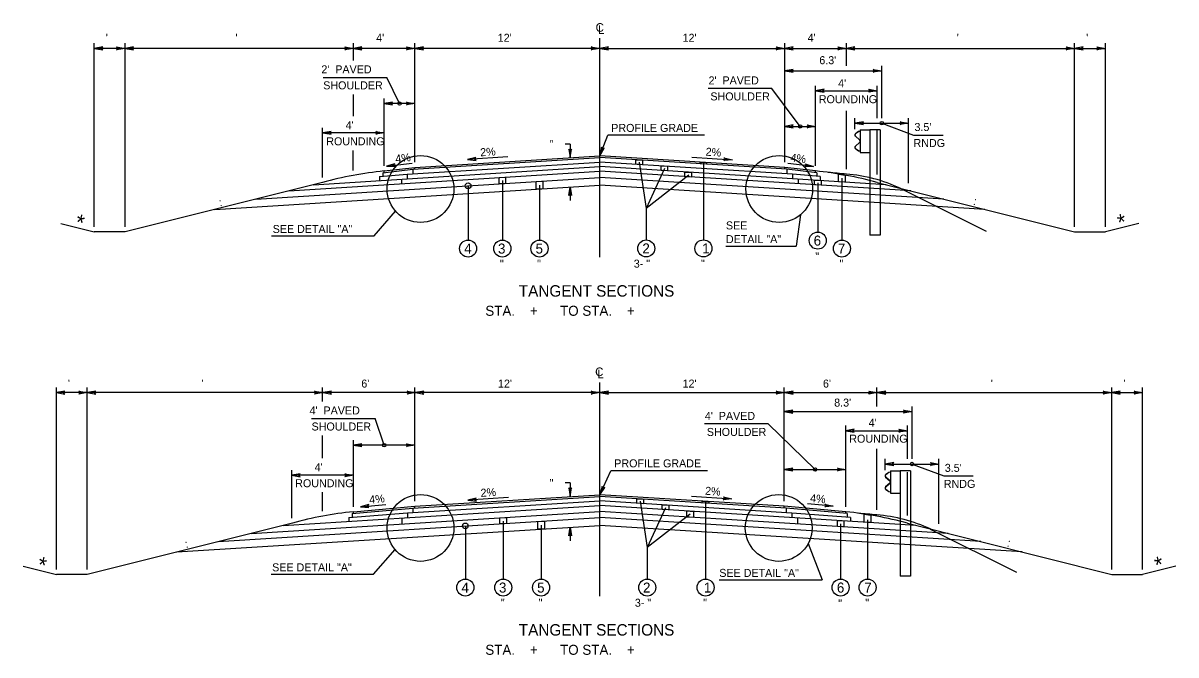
# Model space of a CAD drawing. Extents: x -592 to 1199, y -590 to 416.
# Drawn here: x 137.3 to 338.9, y -214.4 to -104 of the extents above; entities that cross this region are included whole.
import ezdxf

# ---------------------------------------------------------------- set-up
doc = ezdxf.new("R2010")
doc.units = 0
doc.layers.add('1', color=7, linetype='Continuous')
doc.layers.add('Des_ Drain_ Ftrs', color=7, linetype='Continuous')

msp = doc.modelspace()

# ---------------------------------------------------------------- linework, layer by layer
at = {"layer": '1'}
for p, q in [((238.16, -144.86), (238.16, -106.62)), ((149.75, -139.57), (149.75, -107.5)), ((155.13, -108.38), (149.75, -108.38)), ((155.13, -139.57), (155.13, -107.5)), ((195.06, -108.38), (155.13, -108.38)), ((195.06, -110.5), (195.06, -107.5)), ((205.83, -108.38), (195.06, -108.38)), ((205.83, -128.3), (205.83, -107.5)), ((238.16, -108.38), (205.83, -108.38)), ((238.16, -108.38), (270.49, -108.38)), ((270.49, -128.3), (270.49, -107.5)), ((270.49, -108.38), (281.27, -108.38)), ((281.27, -111.45), (281.27, -107.5)), ((281.27, -108.38), (321.19, -108.38)), ((321.19, -139.57), (321.19, -107.5)), ((321.19, -108.38), (326.58, -108.38)), ((326.58, -139.57), (326.58, -107.5)), ((270.49, -112.3), (287.47, -112.3)), ((287.47, -120.58), (287.47, -111.42)), ((189.79, -113.45), (200.93, -113.45)), ((203.14, -118.03), (200.93, -113.45)), ((275.88, -128.93), (275.88, -114.91)), ((286.66, -120.58), (286.66, -114.91)), ((195.06, -120.25), (195.06, -116.46)), ((268.22, -115.38), (257.08, -115.38)), ((273.19, -122.02), (268.22, -115.38)), ((275.88, -115.79), (286.66, -115.79)), ((200.44, -128.93), (200.44, -117.15)), ((205.83, -118.03), (200.44, -118.03)), ((281.27, -129.49), (281.27, -119.32)), ((282.77, -122.53), (282.77, -120.58)), ((292.16, -131.93), (292.16, -120.58)), ((189.66, -130.94), (189.66, -122.26)), ((270.49, -122.02), (275.88, -122.02)), ((282.77, -121.46), (292.16, -121.46)), ((283.37, -122.92), (282.85, -123.31)), ((283.38, -122.95), (282.87, -123.34)), ((283.69, -122.87), (283.37, -122.92)), ((283.69, -122.9), (283.38, -122.95)), ((283.69, -122.64), (283.69, -126.57)), ((283.69, -122.64), (285.37, -122.64)), ((285.37, -122.64), (285.37, -141.04)), ((287.2, -122.64), (285.37, -122.64)), ((286.66, -130.45), (286.66, -122.56)), ((287.2, -122.64), (287.2, -141.04)), ((287.47, -121.46), (293.02, -123.53)), ((200.44, -123.14), (189.67, -123.14)), ((238.16, -127.15), (239.54, -123.57)), ((256.46, -123.57), (239.54, -123.57)), ((282.84, -123.75), (283.57, -124.38)), ((283.57, -124.83), (282.84, -125.47)), ((282.86, -123.72), (283.59, -124.36)), ((283.59, -124.85), (282.86, -125.49)), ((283.66, -124.57), (283.66, -124.64)), ((283.69, -124.57), (283.69, -124.64)), ((293.02, -123.53), (298.18, -123.53)), ((195.05, -129.71), (195.05, -126.21)), ((232.98, -125.1), (232.1, -125.1)), ((232.98, -125.1), (232.98, -127.47)), ((282.85, -125.9), (283.37, -126.29)), ((282.87, -125.88), (283.38, -126.26)), ((283.37, -126.29), (283.69, -126.34)), ((283.38, -126.26), (283.69, -126.31)), ((283.69, -126.57), (285.37, -126.57)), ((200.87, -128.98), (205.34, -128.45)), ((204.48, -130.37), (238.16, -128.25)), ((205.47, -129.5), (238.16, -127.44)), ((205.83, -129.18), (238.16, -127.15)), ((222.09, -127.37), (215.02, -127.82)), ((270.49, -129.18), (238.16, -127.15)), ((270.86, -129.5), (238.16, -127.44)), ((271.84, -130.37), (238.16, -128.25)), ((245.03, -128.28), (246.27, -136.4)), ((254.27, -127.4), (261.34, -127.84)), ((256.27, -128.43), (256.27, -141.86)), ((275.51, -129.01), (271.04, -128.48)), ((178.02, -134.73), (238.16, -130.95)), ((183.79, -133.29), (238.16, -129.87)), ((188.11, -132.21), (238.16, -129.06)), ((199.61, -130.8), (204.48, -130.37)), ((199.61, -130.8), (199.61, -131.49)), ((200.2, -130.14), (205.47, -129.5)), ((200.2, -130.14), (200.2, -130.75)), ((200.44, -129.81), (205.83, -129.18)), ((200.44, -130.11), (200.44, -129.81)), ((204.48, -130.37), (204.48, -131.18)), ((205.47, -129.5), (205.47, -130.31)), ((205.83, -129.48), (205.83, -129.18)), ((288.21, -132.21), (238.16, -129.06)), ((292.54, -133.29), (238.16, -129.87)), ((298.3, -134.73), (238.16, -130.95)), ((249.45, -129.38), (246.27, -136.4)), ((253.72, -130.56), (246.27, -136.4)), ((270.49, -129.48), (270.49, -129.18)), ((275.88, -129.81), (270.49, -129.18)), ((270.86, -129.5), (270.86, -130.31)), ((276.12, -130.14), (270.86, -129.5)), ((271.84, -130.37), (271.84, -131.18)), ((276.71, -130.8), (271.84, -130.37)), ((275.88, -130.11), (275.88, -129.81)), ((276.12, -130.14), (276.12, -130.75)), ((276.71, -130.8), (276.71, -131.48)), ((282.77, -130.59), (282.77, -130.59)), ((189.66, -131.82), (155.13, -140.45)), ((170.82, -136.53), (238.16, -132.3)), ((203.49, -131.24), (203.49, -132.05)), ((215.12, -132.4), (215.12, -141.89)), ((221.11, -131.48), (221.11, -141.89)), ((227.61, -132.29), (227.61, -141.89)), ((232.98, -132.62), (232.98, -134.99)), ((305.51, -136.53), (238.16, -132.3)), ((272.83, -131.24), (272.83, -132.05)), ((276.26, -131.91), (276.26, -140.5)), ((280.49, -131.1), (280.49, -141.89)), ((286.66, -131.82), (321.19, -140.45)), ((290.66, -132.82), (305.71, -140.35)), ((198.7, -141.16), (202.44, -136.84)), ((246.27, -136.4), (246.27, -141.87)), ((143.92, -139), (149.75, -140.45)), ((273.22, -137.48), (272.5, -142.93)), ((332.4, -138.99), (326.58, -140.45)), ((155.13, -140.45), (149.75, -140.45)), ((287.2, -141.04), (285.37, -141.04)), ((321.19, -140.45), (326.58, -140.45)), ((180.76, -141.16), (198.7, -141.16)), ((260.2, -142.93), (272.5, -142.93)), ((238.16, -204.12), (238.16, -166.8)), ((143.13, -199.45), (143.13, -167.68)), ((148.51, -168.56), (143.13, -168.56)), ((148.51, -199.45), (148.51, -167.68)), ((189.76, -168.56), (148.51, -168.56)), ((189.67, -170.11), (189.67, -167.68)), ((205.92, -168.56), (189.76, -168.56)), ((205.83, -187.55), (205.83, -167.68)), ((238.16, -168.56), (205.92, -168.56)), ((238.16, -168.56), (270.49, -168.56)), ((270.4, -187.55), (270.4, -167.68)), ((270.49, -168.56), (286.66, -168.56)), ((286.57, -171), (286.57, -167.68)), ((286.66, -168.56), (327.69, -168.56)), ((327.69, -199.45), (327.69, -167.68)), ((327.69, -168.56), (333.07, -168.56)), ((333.07, -199.45), (333.07, -167.68)), ((292.76, -180.16), (292.76, -171)), ((187.76, -173.08), (198.9, -173.08)), ((200.45, -177.75), (198.9, -173.08)), ((270.4, -171.88), (292.76, -171.88)), ((267.6, -174.03), (256.46, -174.03)), ((275.79, -182), (267.6, -174.03)), ((281.17, -175.21), (291.95, -175.21)), ((281.18, -188.51), (281.18, -174.33)), ((291.96, -180.16), (291.96, -174.33)), ((189.67, -180.02), (189.67, -176.06)), ((195.06, -188.5), (195.06, -176.87)), ((205.83, -177.75), (195.06, -177.75)), ((286.57, -189.07), (286.57, -178.4)), ((288.07, -182.11), (288.07, -180.16)), ((288.07, -181.04), (297.45, -181.04)), ((292.76, -181.04), (298.32, -183.11)), ((297.45, -191.5), (297.45, -180.16)), ((184.28, -190.51), (184.28, -182.12)), ((195.06, -183), (184.28, -183)), ((238.16, -186.4), (240.07, -182.21)), ((256.99, -182.21), (240.07, -182.21)), ((270.4, -182), (281.18, -182)), ((288.14, -183.33), (288.87, -183.96)), ((288.67, -182.5), (288.15, -182.89)), ((288.16, -183.3), (288.89, -183.94)), ((288.68, -182.53), (288.17, -182.92)), ((288.98, -182.45), (288.67, -182.5)), ((288.98, -182.48), (288.68, -182.53)), ((288.98, -182.22), (288.98, -186.15)), ((288.98, -182.22), (290.67, -182.22)), ((290.67, -182.22), (290.67, -200.62)), ((292.49, -182.22), (290.67, -182.22)), ((291.96, -190.03), (291.96, -182.47)), ((292.49, -182.22), (292.49, -200.62)), ((298.32, -183.11), (303.47, -183.11)), ((232.96, -184.35), (232.08, -184.35)), ((232.96, -184.35), (232.96, -186.72)), ((288.87, -184.41), (288.14, -185.05)), ((288.89, -184.43), (288.16, -185.07)), ((288.17, -185.45), (288.68, -185.84)), ((288.95, -184.15), (288.95, -184.22)), ((288.98, -184.15), (288.98, -184.22)), ((189.67, -189.28), (189.67, -185.95)), ((204.5, -189.6), (238.16, -187.49)), ((205.47, -188.75), (238.16, -186.69)), ((205.83, -188.42), (238.16, -186.4)), ((222.16, -186.91), (215.08, -187.35)), ((270.4, -188.43), (238.16, -186.4)), ((270.77, -188.75), (238.16, -186.7)), ((254.16, -186.67), (261.24, -187.12)), ((288.15, -185.48), (288.67, -185.87)), ((288.67, -185.87), (288.98, -185.92)), ((288.68, -185.84), (288.98, -185.89)), ((288.98, -186.15), (290.67, -186.15)), ((177.16, -193.17), (238.16, -189.34)), ((182.78, -191.77), (238.16, -188.28)), ((194.82, -189.7), (205.47, -188.75)), ((195.06, -189.38), (205.83, -188.42)), ((195.06, -189.68), (195.06, -189.38)), ((196.28, -188.5), (200.76, -188.11)), ((205.47, -188.75), (205.47, -189.54)), ((205.83, -188.72), (205.83, -188.42)), ((271.74, -189.61), (238.16, -187.5)), ((293.44, -191.77), (238.16, -188.29)), ((299.06, -193.17), (238.16, -189.34)), ((245.22, -187.56), (246.46, -195.66)), ((249.63, -188.67), (246.46, -195.66)), ((256.65, -187.7), (256.65, -201.15)), ((270.4, -188.73), (270.4, -188.43)), ((281.18, -189.39), (270.4, -188.43)), ((281.42, -189.71), (270.77, -188.75)), ((270.77, -188.75), (270.77, -189.55)), ((278.98, -188.42), (274.5, -188.02)), ((281.18, -189.69), (281.18, -189.39)), ((184.41, -191.36), (148.51, -200.33)), ((171.43, -194.6), (238.16, -190.41)), ((194.26, -190.36), (204.5, -189.6)), ((194.26, -190.36), (194.26, -191.04)), ((194.82, -189.7), (194.82, -190.32)), ((203.53, -190.46), (203.53, -191.51)), ((204.5, -189.6), (204.5, -190.4)), ((221.27, -191.02), (221.27, -201.15)), ((304.78, -194.6), (238.16, -190.41)), ((253.97, -189.78), (246.46, -195.66)), ((271.74, -189.61), (271.74, -190.41)), ((281.98, -190.36), (271.76, -189.62)), ((272.72, -190.47), (272.72, -191.52)), ((280.27, -191.47), (280.27, -201.15)), ((281.42, -189.71), (281.42, -190.32)), ((281.98, -190.36), (281.98, -191.05)), ((284.99, -190.82), (284.99, -201.15)), ((288.07, -190.17), (288.07, -190.17)), ((291.96, -191.4), (327.69, -200.33)), ((164.2, -196.41), (238.16, -191.76)), ((214.64, -191.85), (214.64, -201.15)), ((227.88, -191.75), (227.88, -201.15)), ((232.96, -192.09), (232.96, -194.46)), ((312.01, -196.41), (238.16, -191.77)), ((295.95, -192.4), (311.01, -199.93)), ((274.61, -194.93), (277.04, -201.27)), ((198.6, -200.3), (202.34, -195.98)), ((246.46, -195.66), (246.46, -201.15)), ((137.3, -198.87), (143.13, -200.33)), ((338.9, -198.87), (333.07, -200.33)), ((148.51, -200.33), (143.13, -200.33)), ((180.67, -200.3), (198.6, -200.3)), ((259.04, -201.27), (277.04, -201.27)), ((292.49, -200.62), (290.67, -200.62)), ((327.69, -200.33), (333.07, -200.33))]:
    msp.add_line(p, q, dxfattribs=at)
for points in [[(244.46, -127.84), (245.6, -127.91), (245.6, -128.72), (244.46, -128.65)], [(248.86, -128.93), (250.01, -129), (250.01, -129.81), (248.86, -129.73)], [(255.7, -128.25), (256.84, -128.32), (256.84, -128.62), (255.7, -128.55)], [(220.54, -130.98), (221.68, -130.91), (221.68, -131.99), (220.54, -132.06)], [(253.05, -130), (254.2, -130.07), (254.2, -130.88), (253.05, -130.81)], [(279.92, -130.35), (281.06, -130.55), (281.06, -131.76), (279.92, -131.69)], [(227.04, -131.65), (228.18, -131.58), (228.18, -132.93), (227.04, -133)], [(275.69, -131.42), (276.84, -131.49), (276.84, -132.3), (275.69, -132.23)], [(244.65, -187.11), (245.8, -187.18), (245.8, -187.98), (244.65, -187.9)], [(249.05, -188.18), (250.2, -188.25), (250.2, -189.05), (249.05, -188.98)], [(253.4, -189.25), (254.54, -189.32), (254.54, -190.37), (253.4, -190.3)], [(256.08, -187.53), (257.23, -187.6), (257.23, -187.9), (256.08, -187.83)], [(220.7, -190.43), (221.84, -190.36), (221.84, -191.43), (220.7, -191.5)], [(227.31, -191.09), (228.46, -191.02), (228.46, -192.37), (227.31, -192.44)], [(279.7, -190.91), (280.84, -190.98), (280.84, -192.03), (279.7, -191.96)], [(284.41, -189.8), (285.56, -189.99), (285.56, -191.27), (284.41, -191.2)]]:
    msp.add_lwpolyline(points, close=True, dxfattribs=at)
for centre, radius in [((203.14, -118.03), 0.3), ((273.19, -122.02), 0.3), ((287.47, -121.46), 0.3), ((206.8, -132.96), 5.84), ((269.53, -132.96), 5.84), ((215.12, -132.4), 0.5), ((276.26, -141.99), 1.49), ((215.12, -143.38), 1.49), ((221.11, -143.38), 1.49), ((227.61, -143.38), 1.49), ((246.27, -143.35), 1.49), ((256.27, -143.34), 1.49), ((280.49, -143.38), 1.49), ((200.45, -177.75), 0.3), ((292.76, -181.04), 0.3), ((275.79, -182), 0.3), ((206.8, -192.21), 5.84), ((269.44, -192.21), 5.84), ((214.64, -191.85), 0.5), ((214.64, -202.63), 1.49), ((221.27, -202.63), 1.49), ((227.88, -202.63), 1.49), ((246.46, -202.63), 1.49), ((256.65, -202.63), 1.49), ((280.27, -202.63), 1.49), ((284.99, -202.63), 1.49)]:
    msp.add_circle(centre, radius, dxfattribs=at)
for centre, radius, start, end in [((283.02, -123.54), 0.278, 126.9799, 229.021), ((283.02, -123.54), 0.249, 126.9799, 229.021), ((283.41, -124.57), 0.249, 0, 49.0365), ((283.41, -124.64), 0.249, 310.9635, 0), ((283.41, -124.57), 0.278, 0, 49.0365), ((283.41, -124.64), 0.278, 310.9635, 0), ((283.02, -125.68), 0.278, 130.979, 233.0201), ((283.02, -125.68), 0.249, 130.979, 233.0201), ((207.32, -196.65), 67.19, 95.8795, 105.2381), ((268.99, -196.64), 67.19, 74.7593, 84.1179), ((270.45, -231.03), 101.24, 83.8633, 85.6775), ((279.15, -157.65), 27.37, 65.1374, 85.5513), ((288.32, -183.12), 0.278, 126.9799, 229.021), ((288.32, -183.12), 0.249, 126.9799, 229.021), ((288.32, -185.26), 0.278, 130.979, 233.0201), ((288.32, -185.26), 0.249, 130.979, 233.0201), ((288.71, -184.15), 0.249, 0, 49.0365), ((288.71, -184.22), 0.249, 310.9635, 0), ((288.71, -184.15), 0.278, 0, 49.0365), ((288.71, -184.22), 0.278, 310.9635, 0), ((201.94, -256.22), 67.19, 95.8795, 105.1262), ((274.3, -256.22), 67.19, 74.7611, 84.1196), ((275.75, -290.61), 101.24, 83.8633, 85.6775), ((284.45, -217.23), 27.37, 65.1374, 85.5513)]:
    msp.add_arc(centre, radius, start, end, dxfattribs=at)
at = {"layer": 'Des_ Drain_ Ftrs'}
for points in [[(149.75, -108.38), (151.23, -108.63), (150.94, -108.38), (151.23, -108.13)], [(155.13, -108.38), (153.65, -108.63), (153.94, -108.38), (153.65, -108.13)], [(155.13, -108.38), (156.62, -108.63), (156.33, -108.38), (156.62, -108.13)], [(195.06, -108.38), (193.57, -108.63), (193.86, -108.38), (193.57, -108.13)], [(195.06, -108.38), (196.54, -108.63), (196.25, -108.38), (196.54, -108.13)], [(205.83, -108.38), (204.34, -108.63), (204.64, -108.38), (204.34, -108.13)], [(205.83, -108.38), (207.32, -108.63), (207.03, -108.38), (207.32, -108.13)], [(238.16, -108.38), (236.67, -108.63), (236.97, -108.38), (236.67, -108.13)], [(238.16, -108.38), (239.65, -108.63), (239.36, -108.38), (239.65, -108.13)], [(270.49, -108.38), (269, -108.63), (269.3, -108.38), (269, -108.13)], [(270.49, -108.38), (271.98, -108.63), (271.69, -108.38), (271.98, -108.13)], [(281.27, -108.38), (279.78, -108.63), (280.07, -108.38), (279.78, -108.13)], [(281.27, -108.38), (282.76, -108.63), (282.46, -108.38), (282.76, -108.13)], [(321.19, -108.38), (319.7, -108.63), (319.99, -108.38), (319.7, -108.13)], [(321.19, -108.38), (322.68, -108.63), (322.38, -108.38), (322.68, -108.13)], [(326.58, -108.38), (325.09, -108.63), (325.38, -108.38), (325.09, -108.13)], [(270.49, -112.3), (271.98, -112.55), (271.69, -112.3), (271.98, -112.05)], [(287.47, -112.3), (285.98, -112.55), (286.27, -112.3), (285.98, -112.05)], [(275.88, -115.79), (277.37, -116.04), (277.07, -115.79), (277.37, -115.54)], [(286.66, -115.79), (285.17, -116.04), (285.46, -115.79), (285.17, -115.54)], [(200.44, -118.03), (201.93, -118.28), (201.64, -118.03), (201.93, -117.78)], [(205.83, -118.03), (204.34, -118.28), (204.64, -118.03), (204.34, -117.78)], [(189.67, -123.14), (191.16, -123.39), (190.86, -123.14), (191.16, -122.89)], [(200.44, -123.14), (198.96, -123.39), (199.25, -123.14), (198.96, -122.89)], [(270.49, -122.02), (271.98, -122.27), (271.69, -122.02), (271.98, -121.77)], [(275.88, -122.02), (274.39, -122.27), (274.69, -122.02), (274.39, -121.77)], [(282.77, -121.46), (284.26, -121.7), (283.97, -121.46), (284.26, -121.21)], [(292.16, -121.46), (290.67, -121.7), (290.96, -121.46), (290.67, -121.21)], [(232.98, -127.47), (233.23, -125.98), (232.98, -126.28), (232.73, -125.98)], [(238.16, -127.15), (238.93, -125.84), (238.59, -126.03), (238.46, -125.67)], [(200.87, -128.98), (202.38, -129.05), (202.06, -128.84), (202.32, -128.56)], [(215.02, -127.82), (216.52, -127.97), (216.21, -127.74), (216.49, -127.48)], [(261.34, -127.84), (259.84, -128), (260.15, -127.77), (259.87, -127.5)], [(275.51, -129.01), (274, -129.08), (274.33, -128.87), (274.06, -128.59)], [(232.98, -132.62), (233.23, -134.11), (232.98, -133.82), (232.73, -134.11)], [(143.13, -168.56), (144.61, -168.81), (144.32, -168.56), (144.61, -168.31)], [(148.51, -168.56), (147.03, -168.81), (147.32, -168.56), (147.03, -168.31)], [(148.51, -168.56), (150, -168.81), (149.71, -168.56), (150, -168.31)], [(189.76, -168.56), (188.27, -168.81), (188.57, -168.56), (188.27, -168.31)], [(189.76, -168.56), (191.25, -168.81), (190.95, -168.56), (191.25, -168.31)], [(205.92, -168.56), (204.44, -168.81), (204.73, -168.56), (204.44, -168.31)], [(205.92, -168.56), (207.41, -168.81), (207.12, -168.56), (207.41, -168.31)], [(238.16, -168.56), (236.67, -168.81), (236.97, -168.56), (236.67, -168.31)], [(238.16, -168.56), (239.65, -168.81), (239.36, -168.56), (239.65, -168.31)], [(270.49, -168.56), (269, -168.81), (269.3, -168.56), (269, -168.31)], [(270.49, -168.56), (271.98, -168.81), (271.69, -168.56), (271.98, -168.31)], [(286.66, -168.56), (285.17, -168.81), (285.46, -168.56), (285.17, -168.31)], [(286.66, -168.56), (288.15, -168.81), (287.85, -168.56), (288.15, -168.31)], [(327.69, -168.56), (326.2, -168.81), (326.49, -168.56), (326.2, -168.31)], [(327.69, -168.56), (329.17, -168.81), (328.88, -168.56), (329.17, -168.31)], [(333.07, -168.56), (331.59, -168.81), (331.88, -168.56), (331.59, -168.31)], [(270.4, -171.88), (271.89, -172.13), (271.59, -171.88), (271.89, -171.63)], [(292.76, -171.88), (291.27, -172.13), (291.57, -171.88), (291.27, -171.63)], [(281.17, -175.21), (282.66, -175.45), (282.37, -175.21), (282.66, -174.96)], [(291.95, -175.21), (290.46, -175.45), (290.76, -175.21), (290.46, -174.96)], [(195.06, -177.75), (196.55, -178), (196.25, -177.75), (196.55, -177.5)], [(205.83, -177.75), (204.35, -178), (204.64, -177.75), (204.35, -177.5)], [(288.07, -181.04), (289.56, -181.28), (289.26, -181.04), (289.56, -180.79)], [(297.45, -181.04), (295.97, -181.28), (296.26, -181.04), (295.97, -180.79)], [(184.28, -183), (185.77, -183.25), (185.47, -183), (185.77, -182.75)], [(195.06, -183), (193.57, -183.25), (193.86, -183), (193.57, -182.75)], [(270.4, -182), (271.89, -182.24), (271.6, -182), (271.89, -181.75)], [(281.18, -182), (279.69, -182.24), (279.99, -182), (279.69, -181.75)], [(232.96, -186.72), (233.21, -185.23), (232.96, -185.53), (232.71, -185.23)], [(238.16, -186.4), (239.01, -185.15), (238.66, -185.32), (238.55, -184.95)], [(215.08, -187.35), (216.59, -187.51), (216.27, -187.28), (216.55, -187.01)], [(261.24, -187.12), (259.74, -187.27), (260.05, -187.04), (259.77, -186.78)], [(196.28, -188.5), (197.78, -188.62), (197.47, -188.4), (197.74, -188.13)], [(278.98, -188.42), (277.48, -188.54), (277.79, -188.31), (277.52, -188.04)], [(232.96, -192.09), (233.21, -193.58), (232.96, -193.28), (232.71, -193.58)]]:
    msp.add_lwpolyline(points, close=True, dxfattribs=at)

# ---------------------------------------------------------------- texts
at = {"layer": '1'}
for s, height, p in [(" '", 1.4, (151.24, -107.23)), ("  '", 1.4, (173.4, -107.23)), ("4'", 1.4, (199.05, -107.23)), ("12'", 1.4, (220.3, -107.23)), ("12'", 1.4, (252.63, -107.23)), ("4'", 1.4, (274.49, -107.23)), ("  '", 1.4, (299.53, -107.23)), (" '", 1.4, (322.69, -107.23)), ("6.3'", 1.4, (276.54, -111.15)), ("2'  PAVED", 1.4, (189.46, -112.75)), ('SHOULDER', 1.4, (189.79, -115.55)), ("2'  PAVED", 1.4, (257.17, -114.68)), ("4'", 1.4, (279.84, -115.17)), ('SHOULDER', 1.4, (257.49, -117.48)), ('ROUNDING', 1.4, (276.45, -117.97)), ("4'", 1.4, (193.7, -122.53)), ('PROFILE GRADE', 1.4, (240.15, -122.99)), ("3.5'", 1.4, (293.18, -122.83)), ('ROUNDING', 1.4, (190.32, -125.33)), ('RNDG', 1.4, (293.01, -125.63)), ('SEE', 1.4, (260.21, -140.03)), ('SEE DETAIL "A"', 1.4, (180.95, -140.65)), ('DETAIL "A"', 1.4, (260.21, -142.43)), ('6', 1.75, (275.55, -142.86)), ('4', 1.75, (214.44, -144.25)), ('3', 1.75, (220.35, -144.25)), ('5', 1.75, (226.92, -144.25)), ('2', 1.75, (245.6, -144.23)), ('1', 1.75, (256.06, -144.22)), ('7', 1.75, (279.78, -144.25)), (' "', 1.4, (275.32, -145.44)), (' "', 1.4, (220.17, -146.74)), (' "', 1.4, (226.67, -146.74)), ('3- "', 1.4, (244.09, -146.71)), (' "', 1.4, (255.33, -146.7)), (' "', 1.4, (279.55, -146.74)), ('TANGENT SECTIONS', 2, (223.99, -151.78)), ('STA.    +      TO STA.    +     ', 1.75, (218.13, -155.13)), (" '", 1.4, (144.62, -167.68)), ("  '", 1.4, (167.44, -167.68)), ("6'", 1.4, (196.45, -167.68)), ("12'", 1.4, (220.35, -167.68)), ("12'", 1.4, (252.63, -167.68)), ("6'", 1.4, (277.18, -167.68)), ("  '", 1.4, (305.48, -167.68)), (" '", 1.4, (329.19, -167.68)), ("4'  PAVED", 1.4, (187.4, -172.38)), ("8.3'", 1.4, (279.14, -171)), ("4'  PAVED", 1.4, (256.52, -173.33)), ("4'", 1.4, (285.17, -174.51)), ('SHOULDER', 1.4, (187.75, -175.18)), ('SHOULDER', 1.4, (256.87, -176.13)), ('ROUNDING', 1.4, (281.78, -177.31)), ("4'", 1.4, (188.28, -182.3)), ('PROFILE GRADE', 1.4, (240.68, -181.62)), ("3.5'", 1.4, (298.48, -182.41)), ('ROUNDING', 1.4, (184.89, -185.1)), ('RNDG', 1.4, (298.31, -185.21)), ('SEE DETAIL "A"', 1.4, (180.86, -199.8)), ('SEE DETAIL "A"', 1.4, (259.05, -200.77)), ('4', 1.75, (213.97, -203.51)), ('3', 1.75, (220.52, -203.51)), ('5', 1.75, (227.19, -203.51)), ('2', 1.75, (245.71, -203.51)), ('1', 1.75, (256.35, -203.51)), ('6', 1.75, (279.61, -203.51)), ('7', 1.75, (284.4, -203.51)), (' "', 1.4, (220.33, -205.99)), (' "', 1.4, (226.94, -205.99)), ('3- "', 1.4, (244.28, -205.99)), (' "', 1.4, (255.71, -205.99)), (' "', 1.4, (279.33, -206.09)), ('  "', 1.4, (283.54, -205.99)), ('TANGENT SECTIONS', 2, (223.99, -211.03)), ('STA.    +      TO STA.    +     ', 1.75, (218.13, -214.39))]:
    msp.add_text(s, height=height, dxfattribs=at).set_placement(p)
for s, height, rotation, p in [('  "', 1.4, 0.1438, (228.37, -125.81)), ('4%', 1.4, 6.9824, (202.48, -128.4)), ('2%', 1.4, 3.7204, (217.28, -127.26)), ('2%', 1.4, 356.2798, (256.63, -127.13)), ('4%', 1.4, 353.0228, (271.43, -128.13)), (' : ', 1.4, 14.2282, (171.22, -136.15)), (' : ', 1.4, 345.7718, (302.87, -135.58)), ('*', 2.8, 347.1521, (146.23, -140.02)), ('*', 2.8, 12.8479, (329.04, -140.26)), ('2%', 1.4, 3.7232, (217.35, -186.79)), ('  "', 1.4, 0.1438, (228.35, -185.06)), ('2%', 1.4, 356.2768, (256.53, -186.4)), ('4%', 1.4, 5.3488, (197.9, -187.98)), ('4%', 1.4, 354.6118, (274.88, -187.66)), (' : ', 1.4, 14.2282, (165.28, -195.86)), (' : ', 1.4, 345.7718, (308.77, -195.31)), ('*', 2.8, 347.1521, (139.61, -199.9)), ('*', 2.8, 12.8479, (335.54, -200.14))]:
    msp.add_text(s, height=height, rotation=rotation, dxfattribs=at).set_placement(p)
at = {"layer": 'Des_ Drain_ Ftrs'}
for s, p in [('C', (237.42, -105.48)), ('L', (237.82, -105.88)), ('C', (237.34, -165.67)), ('L', (237.73, -166.06))]:
    msp.add_text(s, height=1.5, dxfattribs=at).set_placement(p)

doc.saveas('drawing.dxf')
